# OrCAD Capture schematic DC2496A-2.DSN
size Custom; note: 100kHz TO 1000MHz DIFFERENTIAL ADC DRIVER/AMPLIFIER
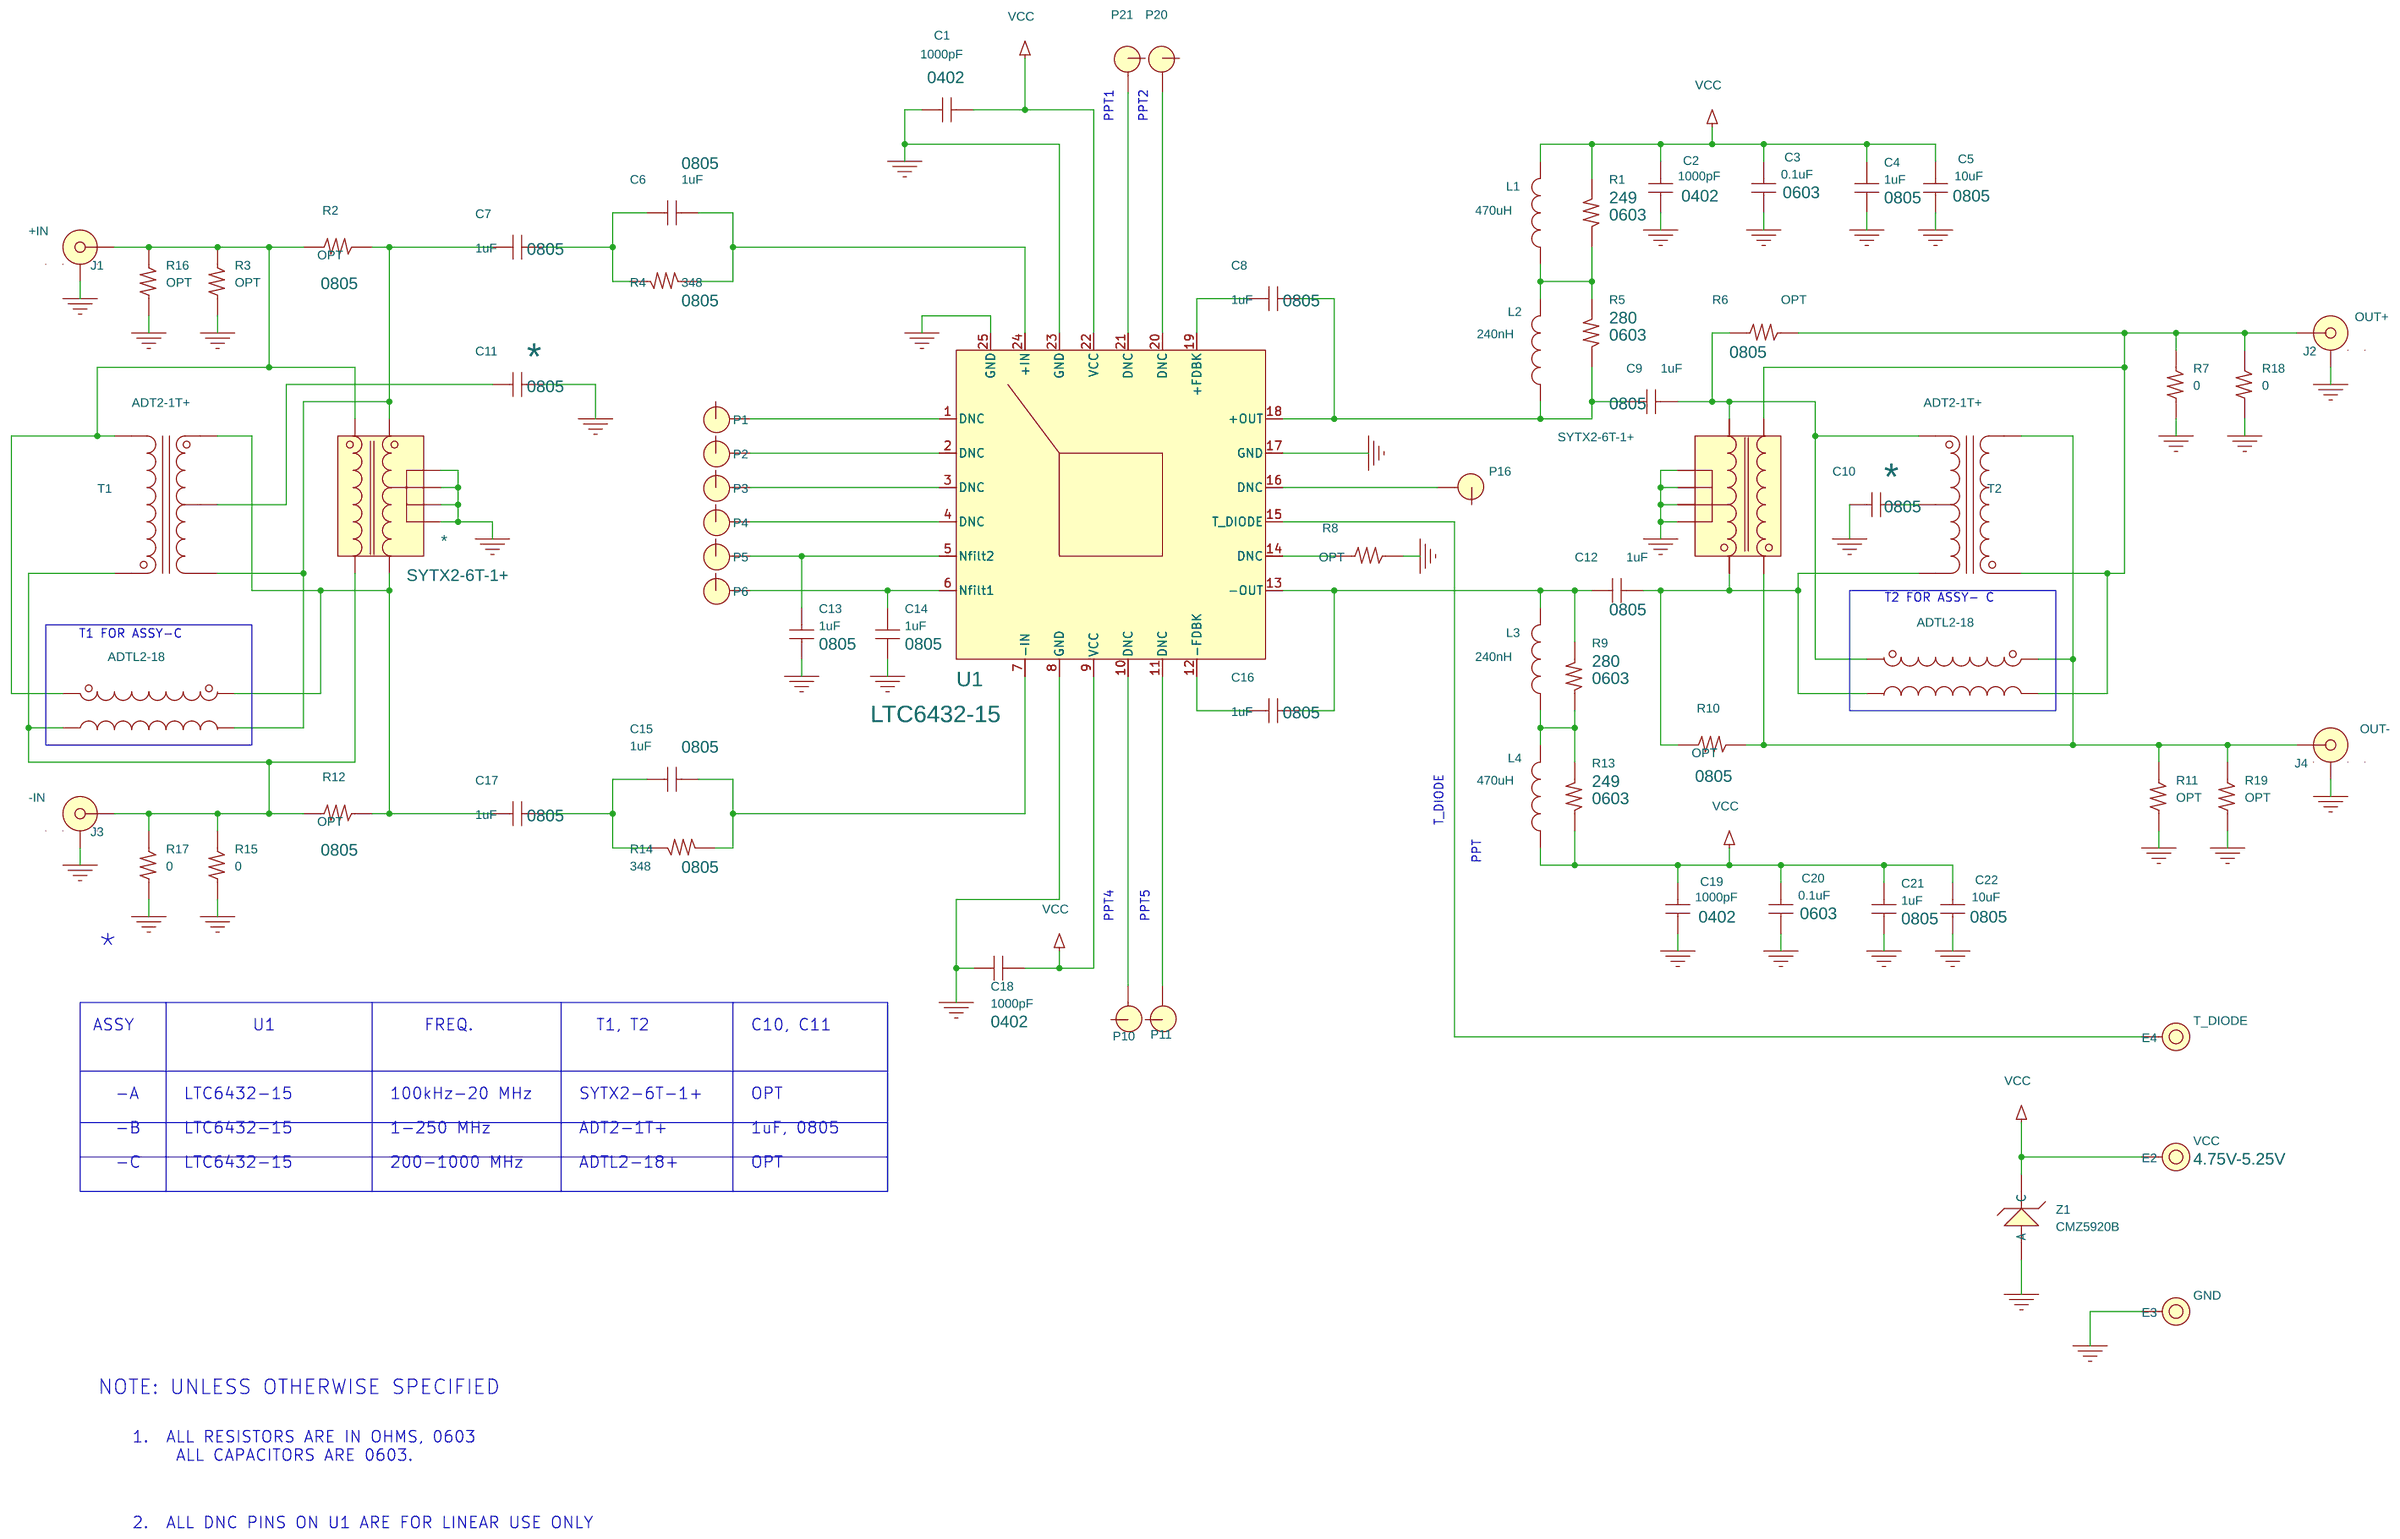
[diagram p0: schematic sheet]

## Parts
C1  1000pF  [0402]
C2  1000pF  [0402]
C3  0.1uF  [0603]
C4  1uF  [0805]
C5  10uF  [0805]
C6  1uF  [0805]
C7  1uF  [0805]
C8  1uF  [0805]
C9  1uF  [0805]
C10  *  [0805]
C11  *  [0805]
C12  1uF  [0805]
C13  1uF  [0805]
C14  1uF  [0805]
C15  1uF  [0805]
C16  1uF  [0805]
C17  1uF  [0805]
C18  1000pF  [0402]
C19  1000pF  [0402]
C20  0.1uF  [0603]
C21  1uF  [0805]
C22  10uF  [0805]
E2  VCC  [MM/2501]
E3  GND  [MM/2501]
E4  T_DIODE  [MM/2501]
J1  +IN  [CON\SMA-END]
J2  OUT+  [CON\SMA-END]
J3  -IN  [CON\SMA-END]
J4  OUT-  [CON\SMA-END]
L1  470uH  [IND-LPS5030]
L2  240nH  [L-0603LS-1608]
L3  240nH  [L-0603LS-1608]
L4  470uH  [IND-LPS5030]
P1  T/H-PAD  [PAD-15X30]
P2  T/H-PAD  [PAD-15X30]
P3  T/H-PAD  [PAD-15X30]
P4  T/H-PAD  [PAD-15X30]
P5  T/H-PAD  [PAD-15X30]
P6  T/H-PAD  [PAD-15X30]
P10  T/H-PAD  [PAD-15X30]
P11  T/H-PAD  [PAD-15X30]
P16  T/H-PAD  [PAD-15X30]
P20  T/H-PAD  [PAD-15X30]
P21  T/H-PAD  [PAD-15X30]
R1  249  [0603]
R2  OPT  [0805]
R3  OPT  [0603]
R4  348  [0805]
R5  280  [0603]
R6  OPT  [0805]
R7  0  [0603]
R8  OPT  [0603]
R9  280  [0603]
R10  OPT  [0805]
R11  OPT  [0603]
R12  OPT  [0805]
R13  249  [0603]
R14  348  [0805]
R15  0  [0603]
R16  OPT  [0603]
R17  0  [0603]
R18  0  [0603]
R19  OPT  [0603]
T1  *  [TRANS-CD542]
T2  SYTX2-6T-1+  [TRANS-CD542]
T3  ADT2-1T+  [TRANS-CD542]
T4  ADT2-1T+  [TRANS-CD542]
T10  ADTL2-18  [TRANS-CD542]
T20  ADTL2-18  [TRANS-CD542]
U1  LTC6432-15  [QFN24UF-4X4]
Z1  CMZ5920B  [DIODE-SMA]

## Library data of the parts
C1-C22 = CAP-NP
E2 = CON_KEY_575-4_0: 5th Part Field: 4.75V-5.25V
E3 E4 = CON_KEY_575-4_0
J1-J4 = CON_SMA-END_3: CONN, BNC, SMA 50-OHM EDGE-LANCH; 1 FILD: 50 Ohm; 2 FILD: 30MHz-3000MHz; Part Number: E.F.JOHNSON, 142-0701-851
L1-L4 = INDUCTOR
P1-P6 P10 P11 P16 P20 P21 = T_H-PAD_0
R1 R9 = R: 1st Part Field: 0; OPT: 250
R2-R4 R6-R8 R10-R12 R14-R19 = R
R5 = R: 1st Part Field: 0
R13 = R: 1st Part Field: 0; OPT: 280
T1 = TRANS-MINI-ADT2-1T_14: 1: SYTX2-6T-1+
T2 = TRANS-MINI-ADT2-1T_14
T3 T4 = TRANS-MINI-ADT2-1T_16
T10 = TRANS-MINI-ADT2-1T_5
T20 = TRANS-MINI-ADT2-1T_6
U1 = LTC643XCUF-QFN24UF-4X4_8
Z1 = ZENER_12V_DDZ9699T_SOD523

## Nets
GND: C1.1 C2.1 C3.1 C4.1 C5.1 C10.2 C11.2 C13.1 C14.1 C18.1 C19.1 C20.1 C21.1 C22.1 E3.1 J1.2(GND) J1.3(GND) J1.4(GND) J1.5(GND) J2.2(GND) J2.3(GND) J2.4(GND) J2.5(GND) J3.2(GND) J3.3(GND) J3.4(GND) J3.5(GND) J4.2(GND) J4.3(GND) J4.4(GND) J4.5(GND) R3.2 R7.2 R8.1 R11.2 R15.2 R16.2 R17.2 R18.2 R19.2 T1.2 T1.3 T1.6 T1.7 T2.2 T2.3 T2.6 T2.7 U1.8(GND) U1.17(GND) U1.23(GND) U1.25(GND) Z1.2(A)
VCC: C1.2 C2.2 C3.2 C4.2 C5.2 C18.2 C19.2 C20.2 C21.2 C22.2 E2.1 L1.2 L4.1 R1.2 R13.1 U1.9(VCC) U1.22(VCC) Z1.1(C)
N16960677: C15.2 R14.2 U1.7(-IN)
N16961369: C6.2 R4.2 U1.24(+IN)
N17686785: R8.2 U1.14(DNC)
N17757621: J1.1(CENTER) R2.2 R3.1 R16.1 T1.1 T3.1 T10.1
N17898778: L1.1 L2.2 R1.1 R5.2
N17898824: C8.2 C9.1 L2.1 R5.1 U1.18(+OUT)
N17898864: C9.2 R6.2 T2.5 T4.6 T20.6
N17899739: C13.2 P5.1 U1.5(Nfilt2)
N17899759: C14.2 P6.1 U1.6(Nfilt1)
N17900307: C6.1 C7.2 R4.1
N17900446: C15.1 C17.2 R14.1
N17901067: C7.1 R2.1 T1.8 T3.4 T10.4
N17901841: C17.1 R12.1 T1.5 T3.6 T10.6
N17901982: J3.1(CENTER) R12.2 R15.1 R17.1 T1.4 T3.3 T10.3
N17902725: P10.1 U1.10(DNC)
N17902728: P11.1 U1.11(DNC)
N17902761: C8.1 U1.19(+FDBK)
N17902777: C16.1 U1.12(-FDBK)
N17902782: C12.1 C16.2 L3.2 R9.2 U1.13(-OUT)
N17903395: L3.1 L4.2 R9.1 R13.2
N17904287: C12.2 R10.2 T2.8 T4.4 T20.4
N17905916: J2.1(CENTER) R6.1 R7.1 R18.1 T2.4 T4.3 T20.3
N17905924: J4.1(CENTER) R10.1 R11.1 R19.1 T2.1 T4.1 T20.1
N17906910: E4.1 U1.15(T_DIODE)
N17915710: P21.1 U1.21(DNC)
N17915712: P20.1 U1.20(DNC)
N17929580: P1.1 U1.1(DNC)
N17929583: P2.1 U1.2(DNC)
N17929586: P3.1 U1.3(DNC)
N17929589: P4.1 U1.4(DNC)
N17929623: P16.1 U1.16(DNC)
N17931442: C11.1 T3.5
N17938313: C10.1 T4.5

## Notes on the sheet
- PPT1
- PPT2
- T2 FOR ASSY- C
- T1 FOR ASSY-C
- T_DIODE
- PPT
- *
- PPT4
- PPT5
- ASSY
- U1
- FREQ.
- T1, T2
- C10, C11
- -A
- LTC6432-15
- 100kHz-20 MHz
- SYTX2-6T-1+
- OPT
- -B
- LTC6432-15
- 1-250 MHz
- ADT2-1T+
- 1uF, 0805
- -C
- LTC6432-15
- 200-1000 MHz
- ADTL2-18+
- OPT
- NOTE: UNLESS OTHERWISE SPECIFIED
- 1.  ALL RESISTORS ARE IN OHMS, 0603
       ALL CAPACITORS ARE 0603.
- 2.  ALL DNC PINS ON U1 ARE FOR LINEAR USE ONLY
